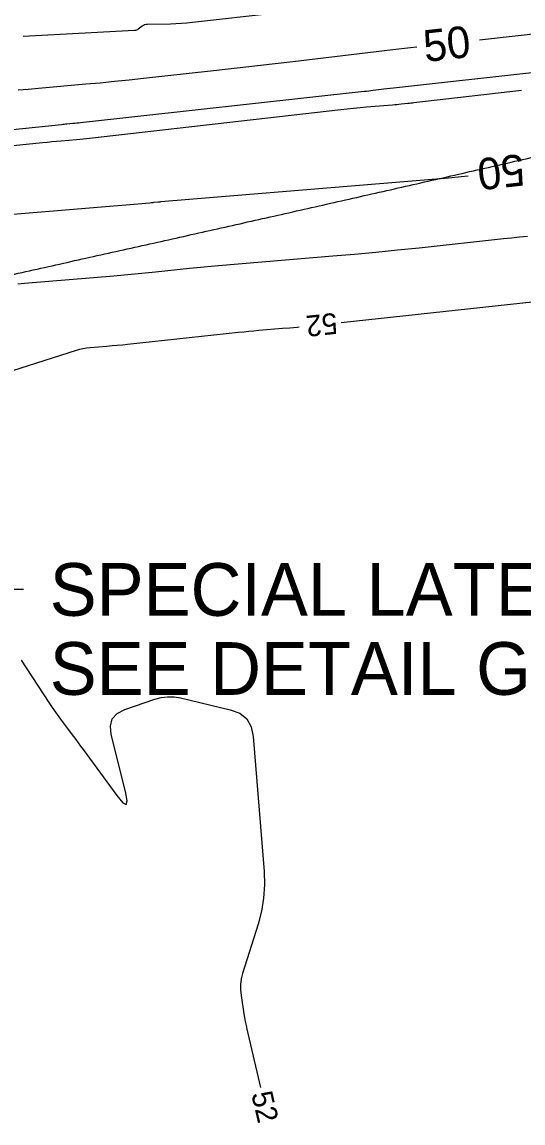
# Model space of a CAD drawing. Extents: x 2384780 to 2405861, y 547869 to 573706.
# Drawn here: x 2390913 to 2390960.6, y 552447.9 to 552552.4 of the extents above; entities that cross this region are included whole.
import ezdxf

# ---------------------------------------------------------------- set-up
doc = ezdxf.new("R2010")
doc.units = 0
for name, color, linetype in [('Old_Level_5', 7, 'Continuous'), ('Old_Level_60', 7, 'Continuous'), ('Old_Level_61', 7, 'Continuous'), ('Old_Level_62', 7, 'Continuous'), ('Old_Level_63', 7, 'Continuous')]:
    doc.layers.add(name, color=color, linetype=linetype)

msp = doc.modelspace()

# ---------------------------------------------------------------- linework, layer by layer
at = {"layer": 'Old_Level_5'}
msp.add_line((2390913.15787, 552498.56184), (2390903.15787, 552498.56184), dxfattribs=at)
at = {"layer": 'Old_Level_60'}
for points in [[(2390953.0565, 552555.056), (2390929.21575, 552552.3475), (2390928.6925, 552552.2945), (2390928.16825, 552552.2545), (2390927.6435, 552552.227), (2390927.11775, 552552.2125), (2390924.943, 552552.179), (2390924.806, 552552.1665), (2390924.67625, 552552.1335), (2390924.55375, 552552.08), (2390924.438, 552552.00575), (2390924.07175, 552551.73), (2390923.99075, 552551.6775), (2390923.905, 552551.63875), (2390923.81425, 552551.61325), (2390923.7185, 552551.60125), (2390913.133, 552551.03375)], [(2390975.72475, 552549.149), (2390948.60075, 552546.15975), (2390948.295, 552546.12575), (2390947.98925, 552546.09125), (2390947.68375, 552546.05575), (2390947.37825, 552546.02), (2390946.3805, 552545.9015), (2390946.16675, 552545.87625), (2390945.95275, 552545.8515), (2390945.73875, 552545.82725), (2390945.52475, 552545.8035), (2390918.582, 552542.833), (2390918.402, 552542.81375), (2390918.22175, 552542.7955), (2390918.0415, 552542.77825), (2390917.86125, 552542.762), (2390917.27175, 552542.711), (2390917.1455, 552542.69975), (2390917.01925, 552542.688), (2390916.89325, 552542.67575), (2390916.767, 552542.663), (2390893.60725, 552540.26125)], [(2390894.227, 552538.84175), (2390914.96575, 552540.9665), (2390915.41075, 552541.011), (2390915.85625, 552541.05325), (2390916.30175, 552541.0935), (2390916.7475, 552541.1315), (2390918.20425, 552541.2525), (2390918.51625, 552541.2795), (2390918.828, 552541.30925), (2390919.1395, 552541.341), (2390919.45075, 552541.3755), (2390943.29725, 552544.10775), (2390943.91125, 552544.1755), (2390944.526, 552544.23825), (2390945.14125, 552544.29575), (2390945.757, 552544.34825), (2390948.22975, 552544.549), (2390948.4305, 552544.566), (2390948.631, 552544.5845), (2390948.83125, 552544.6045), (2390949.0315, 552544.626), (2390949.6855, 552544.69875), (2390949.8255, 552544.7145), (2390949.96575, 552544.73025), (2390950.10575, 552544.74625), (2390950.24575, 552544.76225), (2390960.48025, 552545.93925)], [(2390912.64575, 552527.55575), (2390913.27475, 552527.62575), (2390921.751, 552528.3275), (2390922.74025, 552528.4125), (2390923.729, 552528.50325), (2390924.71725, 552528.60025), (2390925.70475, 552528.703), (2390928.93, 552529.049), (2390929.62125, 552529.121), (2390930.313, 552529.189), (2390931.005, 552529.25275), (2390931.6975, 552529.31225), (2390942.55, 552530.21375), (2390944.5985, 552530.39025), (2390946.64575, 552530.57875), (2390948.692, 552530.7795), (2390950.737, 552530.9925), (2390958.7575, 552531.85175), (2390959.5175, 552531.9335), (2390960.2775, 552532.01625), (2390961.0375, 552532.0995)], [(2390964.10275, 552526.09675), (2390943.3435, 552523.8725)], [(2390939.3655, 552523.4525), (2390939.1495, 552523.43125), (2390938.46175, 552523.368), (2390937.77375, 552523.30875), (2390935.5255, 552523.122), (2390935.044, 552523.0805), (2390934.5625, 552523.03625), (2390934.0815, 552522.989), (2390933.60075, 552522.939), (2390923.054, 552521.808), (2390922.56525, 552521.757), (2390922.07625, 552521.70925), (2390921.58725, 552521.66425), (2390921.09775, 552521.62225), (2390919.49825, 552521.48975), (2390919.1575, 552521.45175), (2390918.82025, 552521.395), (2390918.487, 552521.31925), (2390918.15725, 552521.22475), (2390909.8195, 552518.57475)], [(2390912.941, 552491.85325), (2390915.58825, 552487.8235), (2390915.89125, 552487.37), (2390916.2015, 552486.9215), (2390916.51875, 552486.478), (2390916.843, 552486.0395), (2390917.914, 552484.61525), (2390918.14325, 552484.3095), (2390918.37125, 552484.00325), (2390918.59825, 552483.69625), (2390918.8245, 552483.3885), (2390922.04025, 552478.997), (2390922.608, 552478.315), (2390922.93275, 552478.15125), (2390923.01475, 552478.50575), (2390922.85375, 552479.37825), (2390921.50475, 552484.787), (2390921.41875, 552485.603), (2390921.60525, 552486.27125), (2390922.064, 552486.79175), (2390922.795, 552487.1645), (2390925.62775, 552488.14075), (2390926.237, 552488.30525), (2390926.85075, 552488.38075), (2390927.469, 552488.36725), (2390928.09175, 552488.26475), (2390932.80975, 552487.1535), (2390933.7045, 552486.81575), (2390934.36725, 552486.27875), (2390934.798, 552485.54225), (2390934.9965, 552484.6065), (2390936.01575, 552471.8035), (2390936.05675, 552470.5325), (2390935.9765, 552469.27525), (2390935.77475, 552468.03175), (2390935.4515, 552466.80175), (2390933.9815, 552462.11875), (2390933.85125, 552461.60425), (2390933.78225, 552461.085), (2390933.7745, 552460.5615), (2390933.828, 552460.0335), (2390934.10225, 552458.30125), (2390934.1645, 552457.9305), (2390934.23325, 552457.56125), (2390934.30875, 552457.1935), (2390934.39075, 552456.82675), (2390935.684, 552451.291)]]:
    msp.add_lwpolyline(points, dxfattribs=at)
at = {"layer": 'Old_Level_61'}
for points in [[(2390962.68225, 552551.37425), (2390956.48175, 552550.691)], [(2390950.51925, 552550.021), (2390949.91425, 552549.95125), (2390948.25, 552549.7555), (2390938.745, 552548.627), (2390936.7945, 552548.3975), (2390934.84325, 552548.172), (2390932.8915, 552547.9505), (2390930.9395, 552547.73325), (2390924.56175, 552547.03025), (2390923.19475, 552546.8835), (2390921.827, 552546.74475), (2390920.45825, 552546.61425), (2390919.089, 552546.49175), (2390914.5885, 552546.10225), (2390913.6245, 552546.01675), (2390912.66075, 552545.92725)], [(2390905.29525, 552533.61625), (2390925.17925, 552535.26275), (2390925.28125, 552535.2715), (2390925.38325, 552535.28075), (2390925.48525, 552535.29075), (2390925.587, 552535.3015), (2390925.91975, 552535.337), (2390925.991, 552535.3445), (2390926.0625, 552535.3515), (2390926.13375, 552535.358), (2390926.20525, 552535.36425), (2390953.54375, 552537.6355), (2390953.84475, 552537.66125), (2390954.14575, 552537.689), (2390954.44625, 552537.7185), (2390954.74675, 552537.74975), (2390955.41675, 552537.8215)]]:
    msp.add_lwpolyline(points, dxfattribs=at)
at = {"layer": 'Old_Level_62'}
msp.add_spline([(2390750.412, 552493.903), (2390756.0595, 552495.08775), (2390761.7115, 552496.27325), (2390767.3675, 552497.4605), (2390773.02325, 552498.648), (2390778.6805, 552499.8365), (2390784.343, 552501.02675), (2390790.009, 552502.21875), (2390795.6745, 552503.412), (2390801.34075, 552504.6065), (2390807.0125, 552505.8035), (2390812.6885, 552507.00325), (2390818.36375, 552508.2045), (2390824.04125, 552509.40825), (2390829.7205, 552510.6145), (2390835.4035, 552511.8235), (2390841.09, 552513.036), (2390846.77575, 552514.25075), (2390852.464, 552515.46875), (2390858.15625, 552516.69075), (2390863.84925, 552517.91575), (2390869.5415, 552519.144), (2390875.24, 552520.37675), (2390880.94175, 552521.614), (2390886.6405, 552522.8545), (2390892.34075, 552524.099), (2390898.047, 552525.34875), (2390903.7545, 552526.60325), (2390909.46275, 552527.86225), (2390915.17275, 552529.12625), (2390920.8815, 552530.39475), (2390926.5955, 552531.669), (2390932.311, 552532.949), (2390938.0255, 552534.23375), (2390943.74275, 552535.5245), (2390949.463, 552536.8215), (2390955.18475, 552538.12475), (2390960.9055, 552539.43375), (2390966.629, 552540.74925), (2390972.35275, 552542.071), (2390978.07775, 552543.3995), (2390983.80575, 552544.73525), (2390989.53425, 552546.078), (2390995.26325, 552547.42775), (2391000.9935, 552548.78475), (2391006.72375, 552550.14925), (2391012.45675, 552551.5215), (2391018.19, 552552.9015), (2391023.92225, 552554.289), (2391029.659, 552555.6855), (2391035.39375, 552557.08975), (2391041.12925, 552558.50225), (2391046.8685, 552559.92425), (2391052.60575, 552561.3545), (2391058.344, 552562.79375), (2391064.082, 552564.24175), (2391069.822, 552565.6995), (2391075.56175, 552567.1665), (2391081.29975, 552568.64275), (2391087.04225, 552570.12925), (2391092.784, 552571.626), (2391098.5215, 552573.1315), (2391104.26275, 552574.648), (2391110.00625, 552576.1755), (2391115.74525, 552577.7125), (2391121.4855, 552579.2605), (2391127.227, 552580.81975), (2391132.9685, 552582.39), (2391138.7075, 552583.97075), (2391144.44775, 552585.56325), (2391150.18875, 552587.168), (2391155.9255, 552588.783), (2391161.6655, 552590.41075), (2391167.4045, 552592.05075), (2391173.043, 552593.674)], degree=3, dxfattribs=at)
at = {"layer": 'Old_Level_63'}
msp.add_spline([(2390739.62125, 552545.348), (2390745.271, 552546.5335), (2390750.91725, 552547.7185), (2390756.5675, 552548.904), (2390762.221, 552550.09125), (2390767.8725, 552551.2785), (2390773.5255, 552552.467), (2390779.18075, 552553.6565), (2390784.8375, 552554.848), (2390790.49225, 552556.04), (2390796.14925, 552557.234), (2390801.80925, 552558.43025), (2390807.46975, 552559.62825), (2390813.1315, 552560.8285), (2390818.79225, 552562.031), (2390824.45475, 552563.23575), (2390830.117, 552564.443), (2390835.77825, 552565.6525), (2390841.44475, 552566.86575), (2390847.113, 552568.0825), (2390852.7785, 552569.302), (2390858.44025, 552570.5235), (2390864.10825, 552571.7495), (2390869.779, 552572.98025), (2390875.44625, 552574.2135), (2390881.11525, 552575.4515), (2390886.77975, 552576.6925), (2390892.4515, 552577.9385), (2390898.12275, 552579.18975), (2390903.79025, 552580.444), (2390909.46225, 552581.70425), (2390915.13075, 552582.96875), (2390920.80125, 552584.23825), (2390926.47425, 552585.51375), (2390932.143, 552586.794), (2390937.8135, 552588.0795), (2390943.48575, 552589.3715), (2390949.1565, 552590.66875), (2390954.827, 552591.97225), (2390960.5, 552593.28225), (2390966.17, 552594.5985), (2390971.837, 552595.91975), (2390977.51, 552597.24925), (2390983.1815, 552598.5855), (2390988.84775, 552599.9275), (2390994.51775, 552601.27725), (2391000.18725, 552602.6345), (2391005.85475, 552603.9985), (2391011.52375, 552605.37075), (2391017.19125, 552606.7505), (2391022.85825, 552608.138), (2391028.5255, 552609.534), (2391034.19, 552610.9375), (2391039.85525, 552612.34975), (2391045.51975, 552613.7705), (2391051.18175, 552615.1995), (2391056.84525, 552616.63775), (2391062.50425, 552618.08425), (2391068.1655, 552619.54025), (2391073.82775, 552621.0065), (2391079.48125, 552622.48), (2391085.14025, 552623.9645), (2391090.798, 552625.4595), (2391096.44925, 552626.9625), (2391102.10325, 552628.47625), (2391107.75725, 552630.00125), (2391113.40575, 552631.53525), (2391119.05525, 552633.08025), (2391124.703, 552634.636), (2391130.34475, 552636.2015), (2391135.989, 552637.7785), (2391141.63475, 552639.368), (2391147.27575, 552640.968), (2391152.911, 552642.57825), (2391158.5015, 552644.1875)], degree=3, dxfattribs=at)

# ---------------------------------------------------------------- texts
at = {"layer": 'Old_Level_5'}
for s, p in [('SPECIAL LATERAL V DITCH', (2390915.65787, 552496.06184)), ('SEE DETAIL G', (2390915.65787, 552488.56184))]:
    msp.add_text(s, height=4.9999995, dxfattribs=at).set_placement(p)
at = {"layer": 'Old_Level_60'}
for rotation, p in [(186.0253111, (2390942.8705, 552524.825)), (283.1483333, (2390934.7945, 552450.703))]:
    msp.add_text('52', height=2, rotation=rotation, dxfattribs=at).set_placement(p)
at = {"layer": 'Old_Level_61'}
for rotation, p in [(6.4095694, (2390951.32, 552548.6065)), (186.3202417, (2390960.58125, 552539.90125))]:
    msp.add_text('50', height=3, rotation=rotation, dxfattribs=at).set_placement(p)

doc.saveas('drawing.dxf')
